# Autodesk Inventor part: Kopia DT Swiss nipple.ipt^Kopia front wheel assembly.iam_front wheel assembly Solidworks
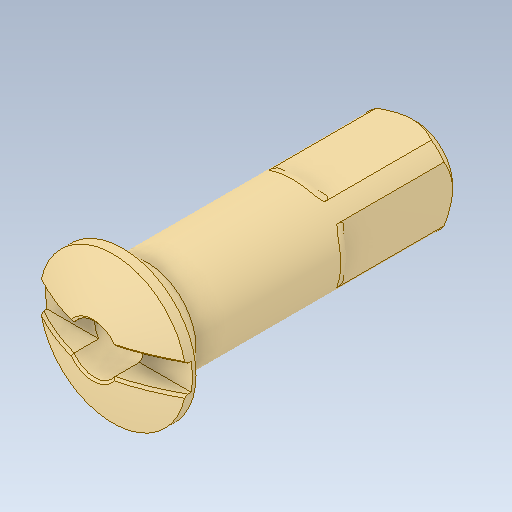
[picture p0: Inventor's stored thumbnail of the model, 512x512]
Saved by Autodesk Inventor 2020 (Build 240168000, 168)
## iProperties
Created: 2017-09
Part Number: Kopia DT Swiss nipple.ipt^Kopia front wheel assembly.iam_front wheel assembly Solidworks
Material: Ogólny
Document SubType Name: Modeling
Designer: Tomasz
Density: 1 g/cm^3
Appearance: Domyślna
Sending System: SolidWorks 2017
Last Author: Tomasz
Last Saved: 2017-09-11
Author: Tomasz
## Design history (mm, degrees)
feature "DT Swiss nipple.ipt"
node "Bryła1"
